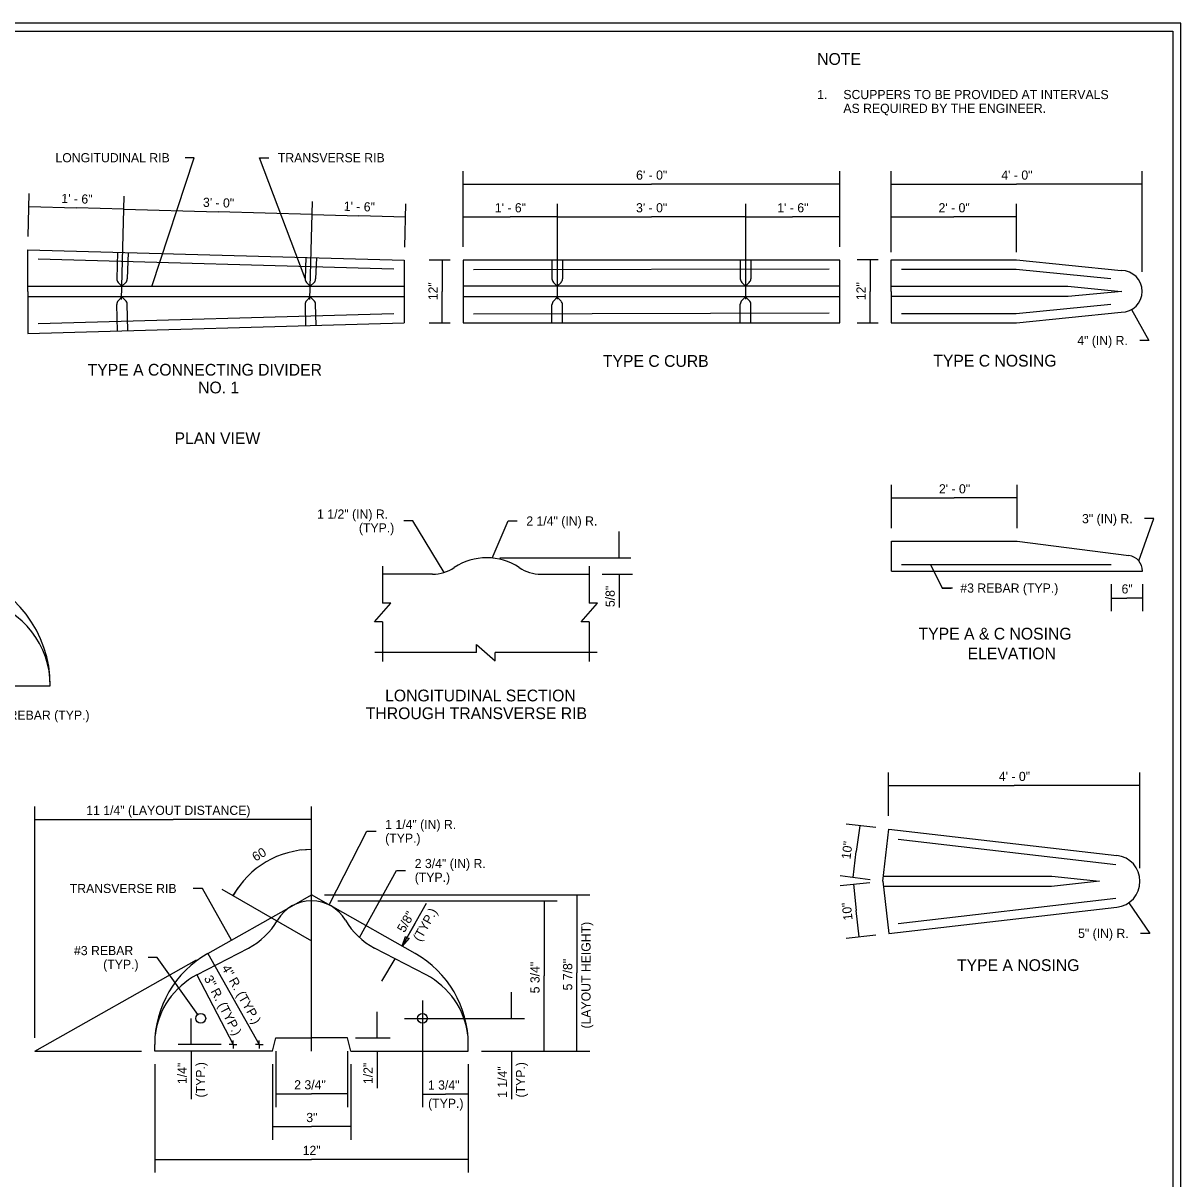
# Model space of a CAD drawing. Extents: x 99988 to 100172, y 99995 to 100047.
# Drawn here: x 100006.96 to 100015.81, y 100001.6 to 100010.44 of the extents above; entities that cross this region are included whole.
import ezdxf

# ---------------------------------------------------------------- set-up
doc = ezdxf.new("R2010")
doc.units = 0
for name, color, linetype in [('Level 1', 7, 'Continuous'), ('Level 15', 7, 'Continuous'), ('Level 2', 7, 'Continuous'), ('Level 20', 7, 'Continuous'), ('Level 27', 7, 'Continuous'), ('Level 3', 7, 'Continuous'), ('SH_GI_PlotLimits', 7, 'Continuous'), ('SH_GI_SheetBorder', 7, 'Continuous'), ('SH_RS_ConstructionNoteFlag', 7, 'Continuous'), ('SH_RS_DimensionLines', 7, 'Continuous')]:
    doc.layers.add(name, color=color, linetype=linetype)

msp = doc.modelspace()

# ---------------------------------------------------------------- linework, layer by layer
at = {"layer": 'Level 1'}
for centre in [(100008.318, 100002.8241), (100010.0134, 100002.8241)]:
    msp.add_circle(centre, 0.0375, dxfattribs=at)
at = {"layer": 'Level 15'}
for p, q in [((100010.324, 100008.7252), (100010.324, 100009.3052)), ((100013.204, 100008.7252), (100013.204, 100009.3052)), ((100013.5969, 100008.6857), (100013.5969, 100009.3052)), ((100015.5169, 100008.536), (100015.5169, 100009.3052)), ((100010.324, 100009.2052), (100011.764, 100009.2052)), ((100013.204, 100009.2052), (100011.764, 100009.2052)), ((100013.5969, 100009.2052), (100014.5569, 100009.2052)), ((100015.5169, 100009.2052), (100014.5569, 100009.2052)), ((100006.9972, 100008.8043), (100007.0063, 100009.1342)), ((100007.7116, 100008.3239), (100007.7335, 100009.114)), ((100007.0036, 100009.0342), (100007.3672, 100009.0241)), ((100007.7308, 100009.014), (100007.3672, 100009.0241)), ((100007.7308, 100009.014), (100008.4502, 100008.994)), ((100009.1697, 100008.9741), (100008.4502, 100008.994)), ((100009.1516, 100008.3239), (100009.1724, 100009.074)), ((100009.8772, 100008.7243), (100009.8863, 100009.0542)), ((100011.0441, 100009.0552), (100011.0441, 100008.3255)), ((100012.4836, 100009.0552), (100012.4836, 100008.3255)), ((100014.5569, 100008.6857), (100014.5569, 100009.0552)), ((100009.1697, 100008.9741), (100009.5266, 100008.9641)), ((100009.8836, 100008.9542), (100009.5266, 100008.9641)), ((100010.324, 100008.9552), (100010.684, 100008.9552)), ((100011.0441, 100008.9552), (100010.684, 100008.9552)), ((100011.0441, 100008.9552), (100011.7638, 100008.9552)), ((100012.4836, 100008.9552), (100011.7638, 100008.9552)), ((100012.4836, 100008.9752), (100012.4837, 100008.9752)), ((100012.4836, 100008.9552), (100012.8438, 100008.9552)), ((100013.204, 100008.9552), (100012.8438, 100008.9552)), ((100013.5969, 100008.9552), (100014.0769, 100008.9552)), ((100014.5569, 100008.9552), (100014.0769, 100008.9552)), ((100010.224, 100008.6252), (100010.064, 100008.6252)), ((100010.164, 100008.6252), (100010.164, 100008.3852)), ((100013.4969, 100008.6257), (100013.3369, 100008.6257)), ((100013.4369, 100008.6257), (100013.4369, 100008.3857)), ((100010.164, 100008.1452), (100010.164, 100008.3852)), ((100013.4369, 100008.1457), (100013.4369, 100008.3857)), ((100010.064, 100008.1452), (100010.224, 100008.1452)), ((100013.3369, 100008.1457), (100013.4969, 100008.1457)), ((100013.6, 100006.5752), (100013.6, 100006.9052)), ((100014.56, 100006.5752), (100014.56, 100006.9052)), ((100013.6, 100006.8052), (100014.08, 100006.8052)), ((100014.56, 100006.8052), (100014.08, 100006.8052)), ((100010.605, 100006.3477), (100011.6059, 100006.3477)), ((100009.7085, 100006.2827), (100009.7085, 100006)), ((100011.2885, 100006.2827), (100011.2885, 100006)), ((100011.3885, 100006.2227), (100011.6185, 100006.2227)), ((100014.0663, 100006.116), (100013.9863, 100006.116)), ((100015.52, 100006.1452), (100015.52, 100005.9397)), ((100009.6462, 100005.8565), (100009.7708, 100006)), ((100009.7708, 100006), (100009.7085, 100006)), ((100011.2262, 100005.8565), (100011.3508, 100006)), ((100011.3508, 100006), (100011.2885, 100006)), ((100009.7085, 100005.8565), (100009.6462, 100005.8565)), ((100009.7085, 100005.8565), (100009.7085, 100005.5549)), ((100011.2885, 100005.8565), (100011.2262, 100005.8565)), ((100011.2885, 100005.8565), (100011.2885, 100005.5549)), ((100010.4267, 100005.6227), (100010.4267, 100005.685)), ((100010.4267, 100005.685), (100010.5703, 100005.5604)), ((100010.4267, 100005.6227), (100009.6485, 100005.6227)), ((100011.3485, 100005.6227), (100010.5703, 100005.6227)), ((100010.5703, 100005.5604), (100010.5703, 100005.6227)), ((100013.5765, 100004.3737), (100013.5765, 100004.7054)), ((100015.5001, 100003.9726), (100015.5001, 100004.7054)), ((100013.5765, 100004.6054), (100014.5383, 100004.6054)), ((100015.5001, 100004.6054), (100014.5383, 100004.6054)), ((100007.0499, 100002.6742), (100007.0499, 100004.4459)), ((100009.1647, 100002.5742), (100009.1647, 100004.4459)), ((100007.0499, 100004.3459), (100008.1073, 100004.3459)), ((100009.1647, 100004.3459), (100008.1073, 100004.3459)), ((100013.357, 100004.2973), (100013.3292, 100004.1005)), ((100009.1647, 100004.1158), (100009.0899, 100004.1117)), ((100013.3069, 100003.903), (100013.3292, 100004.1005)), ((100008.4793, 100003.8133), (100009.1647, 100003.4176)), ((100008.5659, 100003.7633), (100008.6056, 100003.8265)), ((100013.3082, 100003.8501), (100013.3304, 100003.6487)), ((100009.2647, 100003.7687), (100011.2936, 100003.7687)), ((100009.3661, 100003.7242), (100011.0436, 100003.7242)), ((100010.9436, 100003.7242), (100010.9436, 100003.1492)), ((100011.1936, 100003.7687), (100011.1936, 100003.1715)), ((100013.3531, 100003.4475), (100013.3304, 100003.6487)), ((100009.8593, 100003.3757), (100009.938, 100003.5152)), ((100008.3725, 100003.3209), (100008.7658, 100002.6242)), ((100008.2877, 100003.1565), (100008.5647, 100002.6242)), ((100011.1936, 100002.5742), (100011.1936, 100003.1715)), ((100010.9436, 100002.5742), (100010.9436, 100003.1492)), ((100010.6936, 100002.8241), (100010.6936, 100003.0241)), ((100008.2455, 100002.6242), (100008.2455, 100002.8242)), ((100009.6674, 100002.6742), (100009.6674, 100002.8742)), ((100008.4747, 100002.6242), (100008.1455, 100002.6242)), ((100009.5025, 100002.6742), (100009.7674, 100002.6742)), ((100008.8912, 100002.5742), (100008.8912, 100002.146)), ((100010.4636, 100002.5742), (100011.2936, 100002.5742)), ((100007.9658, 100002.4742), (100007.9658, 100001.6442)), ((100008.8662, 100002.4742), (100008.8662, 100001.8959)), ((100009.4657, 100002.4742), (100009.4657, 100001.8959)), ((100010.3636, 100002.4742), (100010.3636, 100001.6442)), ((100008.8912, 100002.246), (100009.166, 100002.246)), ((100009.4407, 100002.246), (100009.166, 100002.246)), ((100010.0134, 100002.2442), (100010.1885, 100002.2442)), ((100010.3636, 100002.2442), (100010.1885, 100002.2442)), ((100008.8662, 100001.9959), (100009.166, 100001.9959)), ((100009.4657, 100001.9959), (100009.166, 100001.9959)), ((100007.9658, 100001.7442), (100009.1647, 100001.7442)), ((100010.3636, 100001.7442), (100009.1647, 100001.7442))]:
    msp.add_line(p, q, dxfattribs=at)
for points in [[(100007.9439, 100008.4239), (100008.2686, 100009.4081), (100008.1986, 100009.4081)], [(100009.1159, 100008.4829), (100008.7676, 100009.4081), (100008.8376, 100009.4081)], [(100015.4353, 100008.2463), (100015.5685, 100008.0093), (100015.4985, 100008.0093)], [(100010.1787, 100006.236), (100009.9406, 100006.6292), (100009.8706, 100006.6292)], [(100010.5458, 100006.3459), (100010.6675, 100006.6292), (100010.7375, 100006.6292)], [(100015.4902, 100006.3244), (100015.6049, 100006.6471), (100015.5349, 100006.6471)], [(100013.8993, 100006.2952), (100013.9863, 100006.116), (100014.0563, 100006.116)], [(100015.28, 100006.1452), (100015.28, 100005.9397)], [(100009.3009, 100003.6915), (100009.5881, 100004.2551), (100009.6581, 100004.2551)], [(100009.5306, 100003.4431), (100009.8142, 100003.9561), (100009.8842, 100003.9561)], [(100008.5519, 100003.4221), (100008.3305, 100003.818), (100008.2605, 100003.818)], [(100015.4137, 100003.708), (100015.5747, 100003.4746), (100015.5047, 100003.4746)], [(100008.2962, 100002.8547), (100007.9852, 100003.29), (100007.9152, 100003.29)]]:
    msp.add_lwpolyline(points, dxfattribs=at)
msp.add_lwpolyline([(100009.8593, 100003.3757), (100009.8845, 100003.4517), (100009.8961, 100003.441), (100009.9113, 100003.4366)], close=True, dxfattribs=at)
msp.add_arc((100009.1647, 100003.431), 0.6849, 90, 150.96723, dxfattribs=at)
at = {"layer": 'Level 2'}
for p, q in [((100006.9944, 100008.3844), (100006.9944, 100008.7044)), ((100006.9944, 100008.7044), (100009.8744, 100008.6244)), ((100007.6813, 100008.6865), (100007.6756, 100008.4827)), ((100007.7619, 100008.682), (100007.7563, 100008.4805)), ((100009.1211, 100008.6453), (100009.1159, 100008.4829)), ((100009.2018, 100008.6418), (100009.1966, 100008.4803)), ((100009.7944, 100008.556), (100007.0744, 100008.6309)), ((100009.8744, 100008.6244), (100009.8744, 100008.1444)), ((100013.124, 100008.5557), (100010.404, 100008.5495)), ((100011.0036, 100008.6252), (100011.0036, 100008.4825)), ((100011.0844, 100008.6252), (100011.0844, 100008.4825)), ((100012.4436, 100008.6252), (100012.4436, 100008.4825)), ((100012.5244, 100008.6252), (100012.5244, 100008.4825)), ((100007.7144, 100008.4247), (100007.6865, 100008.4541)), ((100007.7144, 100008.4247), (100007.7438, 100008.4525)), ((100009.1544, 100008.4247), (100009.1267, 100008.4543)), ((100009.1544, 100008.4247), (100009.184, 100008.4524)), ((100011.044, 100008.4255), (100011.0153, 100008.4542)), ((100011.044, 100008.4255), (100011.0727, 100008.4542)), ((100012.484, 100008.4255), (100012.4553, 100008.4542)), ((100012.484, 100008.4255), (100012.5127, 100008.4542)), ((100013.5969, 100008.3857), (100013.5969, 100008.1457)), ((100007.6809, 100008.0821), (100007.675, 100008.2856)), ((100007.7138, 100008.3437), (100007.6859, 100008.3142)), ((100007.7138, 100008.3437), (100007.7432, 100008.3158)), ((100007.7615, 100008.0867), (100007.7558, 100008.2879)), ((100009.1151, 100008.2856), (100009.1199, 100008.1199)), ((100009.1538, 100008.3437), (100009.126, 100008.3142)), ((100009.1538, 100008.3437), (100009.1833, 100008.3158)), ((100009.2005, 100008.1267), (100009.1958, 100008.2879)), ((100011.044, 100008.3405), (100011.0153, 100008.3119)), ((100011.044, 100008.3405), (100011.0727, 100008.3119)), ((100012.4436, 100008.1452), (100012.4436, 100008.2879)), ((100012.484, 100008.3448), (100012.4553, 100008.3162)), ((100012.484, 100008.3448), (100012.5127, 100008.3162)), ((100012.5244, 100008.1453), (100012.5244, 100008.2879)), ((100009.7944, 100008.2132), (100007.0744, 100008.1382)), ((100013.124, 100008.218), (100010.404, 100008.2118)), ((100011.0036, 100008.1452), (100011.0036, 100008.2836)), ((100011.0844, 100008.1452), (100011.0844, 100008.2836)), ((100014.56, 100006.4752), (100015.4155, 100006.3642)), ((100013.6769, 100006.2952), (100015.28, 100006.2952)), ((100010.0904, 100006.2227), (100009.7085, 100006.2227)), ((100013.6, 100006.2452), (100015.52, 100006.2452)), ((100005.255, 100005.3684), (100007.1675, 100005.3684)), ((100013.5349, 100003.8726), (100013.5801, 100004.2726)), ((100013.5801, 100004.2726), (100015.3231, 100004.0713)), ((100013.6518, 100004.194), (100015.3151, 100004.0019)), ((100013.5349, 100003.8726), (100013.5801, 100003.4726)), ((100008.3725, 100003.3209), (100009.033, 100003.6938)), ((100009.033, 100003.6938), (100009.1647, 100003.7681)), ((100009.3114, 100003.6859), (100009.1647, 100003.7681)), ((100013.6518, 100003.5512), (100015.3151, 100003.7434)), ((100009.9569, 100003.3209), (100009.3275, 100003.6762)), ((100013.5801, 100003.4726), (100015.3231, 100003.6739)), ((100008.2877, 100003.1565), (100008.6824, 100003.3618)), ((100010.0417, 100003.1565), (100009.647, 100003.3618)), ((100007.0499, 100002.5742), (100008.2854, 100003.2717)), ((100008.3725, 100003.3209), (100008.3725, 100003.3209)), ((100010.0134, 100002.9616), (100010.0134, 100002.1442)), ((100010.258, 100002.9657), (100010.258, 100002.9657)), ((100009.8759, 100002.8241), (100010.7936, 100002.8241)), ((100007.9658, 100002.5742), (100007.9658, 100002.6242)), ((100008.5647, 100002.6242), (100008.5347, 100002.6242)), ((100008.5647, 100002.6242), (100008.5647, 100002.6542)), ((100008.5647, 100002.6242), (100008.5647, 100002.5942)), ((100008.5647, 100002.6242), (100008.5947, 100002.6242)), ((100008.7658, 100002.6242), (100008.7358, 100002.6242)), ((100008.7658, 100002.6242), (100008.7658, 100002.6542)), ((100008.7658, 100002.6242), (100008.7658, 100002.5942)), ((100008.7658, 100002.6242), (100008.7958, 100002.6242)), ((100008.8662, 100002.5742), (100008.8912, 100002.6742)), ((100009.4407, 100002.6742), (100009.1657, 100002.6742)), ((100009.4657, 100002.5742), (100009.4407, 100002.6742)), ((100010.3636, 100002.5742), (100010.3636, 100002.6242)), ((100007.0499, 100002.5742), (100007.8658, 100002.5742)), ((100008.8662, 100002.5742), (100007.9658, 100002.5742)), ((100009.4407, 100002.5742), (100009.4407, 100002.1522)), ((100009.4657, 100002.5742), (100010.3636, 100002.5742)), ((100009.4407, 100002.1824), (100009.4407, 100002.146))]:
    msp.add_line(p, q, dxfattribs=at)
for points in [[(100010.324, 100008.1452), (100013.204, 100008.1452), (100013.204, 100008.6252), (100010.324, 100008.6252), (100010.324, 100008.1452)], [(100013.5969, 100008.6257), (100014.5569, 100008.6257), (100015.3569, 100008.5457)], [(100013.5969, 100008.3857), (100013.5969, 100008.6257)], [(100013.5969, 100008.6257), (100014.5569, 100008.6257), (100015.3569, 100008.5457)], [(100013.6769, 100008.5559), (100014.5534, 100008.5559), (100015.2769, 100008.4835)], [(100006.9944, 100008.3844), (100006.9944, 100008.0644), (100009.8744, 100008.1444)], [(100013.6769, 100008.2156), (100014.5534, 100008.2156), (100015.2769, 100008.288)], [(100013.5969, 100008.1457), (100014.5569, 100008.1457), (100015.3569, 100008.2257)], [(100013.6, 100006.2452), (100013.6, 100006.4752), (100014.56, 100006.4752)], [(100010.9195, 100006.2227), (100011.2885, 100006.2227)], [(100008.8912, 100002.6742), (100009.1662, 100002.6742)], [(100009.4407, 100002.6742), (100009.1657, 100002.6742)]]:
    msp.add_lwpolyline(points, dxfattribs=at)
for centre, radius, start, end in [((100007.7156, 100008.4816), 0.04, 178.40886, 223.40886), ((100007.7164, 100008.4816), 0.04, 313.40886, 358.40886), ((100009.1559, 100008.4816), 0.04, 178.15574, 223.15574), ((100009.1566, 100008.4816), 0.04, 313.15574, 358.15574), ((100011.0436, 100008.4825), 0.04, 180, 225), ((100011.0444, 100008.4825), 0.04, 315, 0), ((100012.4836, 100008.4825), 0.04, 180, 225), ((100012.4844, 100008.4825), 0.04, 315, 0), ((100015.3569, 100008.3857), 0.16, 270, 90), ((100007.715, 100008.2867), 0.04, 136.64208, 181.64208), ((100007.7158, 100008.2867), 0.04, 1.64208, 46.64208), ((100009.1551, 100008.2867), 0.04, 136.678, 181.678), ((100009.1558, 100008.2867), 0.04, 1.678, 46.678), ((100011.0436, 100008.2836), 0.04, 135, 180), ((100011.0444, 100008.2836), 0.04, 0, 45), ((100012.4836, 100008.2879), 0.04, 135, 180), ((100012.4844, 100008.2879), 0.04, 0, 45), ((100010.505, 100005.8977), 0.45, 56.44269, 123.55731), ((100015.4, 100006.2452), 0.12, 0, 82.60746), ((100010.0904, 100006.5227), 0.3, 270, 303.55731), ((100010.9195, 100006.5227), 0.3, 236.44269, 270), ((100006.2675, 100005.3684), 0.9, 0, 74.83771), ((100006.4925, 100005.3684), 0.675, 0, 75.66199), ((100015.3001, 100003.8726), 0.2, 276.58881, 83.41119), ((100009.1647, 100003.4242), 0.3, 90, 149.97217), ((100009.1647, 100003.4242), 0.3, 30.02783, 90), ((100008.4285, 100003.8497), 0.55, 297.49016, 329.97217), ((100009.9009, 100003.8497), 0.55, 210.02783, 242.50984), ((100008.7658, 100002.6242), 0.8, 119.44692, 180), ((100009.5636, 100002.6242), 0.8, 0, 60.55308), ((100008.5647, 100002.6242), 0.6, 117.49125, 173.12025), ((100009.7647, 100002.6242), 0.6, 6.87975, 62.50875)]:
    msp.add_arc(centre, radius, start, end, dxfattribs=at)
at = {"layer": 'Level 27'}
for p, q in [((100009.8744, 100008.4239), (100006.9944, 100008.4239)), ((100013.1969, 100008.4255), (100010.324, 100008.4255)), ((100013.5969, 100008.4261), (100014.9473, 100008.4261)), ((100014.9473, 100008.4261), (100015.3569, 100008.3857)), ((100015.3609, 100008.3857), (100014.9513, 100008.3454)), ((100009.8744, 100008.344), (100006.9944, 100008.344)), ((100013.1965, 100008.3448), (100010.324, 100008.3448)), ((100014.9513, 100008.3454), (100013.5969, 100008.3454)), ((100013.5395, 100003.913), (100014.825, 100003.913)), ((100015.1917, 100003.8726), (100014.8233, 100003.8323)), ((100014.825, 100003.913), (100015.1917, 100003.8728)), ((100014.8233, 100003.8323), (100013.5395, 100003.8323))]:
    msp.add_line(p, q, dxfattribs=at)
at = {"layer": 'Level 3'}
for p, q in [((100013.4808, 100004.2837), (100013.2522, 100004.3092)), ((100013.4357, 100003.8852), (100013.2075, 100003.9142)), ((100013.4355, 100003.8623), (100013.2083, 100003.8388)), ((100013.4808, 100003.4616), (100013.2538, 100003.4362))]:
    msp.add_line(p, q, dxfattribs=at)
at = {"layer": 'SH_GI_PlotLimits'}
msp.add_lwpolyline([(99999.3125, 99999.9375), (100015.8125, 99999.9375), (100015.8125, 100010.4375), (99999.3125, 100010.4375)], close=True, dxfattribs=at)
at = {"layer": 'SH_GI_SheetBorder'}
for p, q in [((100000, 100010.375), (100015.75, 100010.375)), ((100015.75, 100010.375), (100015.75, 100000))]:
    msp.add_line(p, q, dxfattribs=at)
at = {"layer": 'SH_RS_DimensionLines'}
for p, q in [((100011.5185, 100006.3477), (100011.5185, 100006.5477)), ((100011.5185, 100006.2227), (100011.5185, 100005.9666)), ((100015.28, 100006.0397), (100015.4, 100006.0397)), ((100015.52, 100006.0397), (100015.4, 100006.0397)), ((100009.8593, 100003.3757), (100010.0451, 100003.7049)), ((100009.8593, 100003.3757), (100009.9576, 100003.5498)), ((100009.803, 100003.2806), (100009.7012, 100003.1085)), ((100008.2455, 100002.5742), (100008.2455, 100002.2058)), ((100009.6674, 100002.5742), (100009.6674, 100002.2915)), ((100010.6936, 100002.5742), (100010.6936, 100002.2058))]:
    msp.add_line(p, q, dxfattribs=at)

# ---------------------------------------------------------------- texts
at = {"layer": 'Level 20'}
for s, height, p in [('NOTE', 0.09, (100013.0318, 100010.1184)), ('1.', 0.07, (100013.0318, 100009.8564)), ('SCUPPERS TO BE PROVIDED AT INTERVALS', 0.07, (100013.2318, 100009.8564)), ('AS REQUIRED BY THE ENGINEER.', 0.07, (100013.2318, 100009.7508)), ('LONGITUDINAL RIB', 0.07, (100007.2068, 100009.3731)), ('6\' - 0"', 0.07, (100011.6468, 100009.2402)), ('4\' - 0"', 0.07, (100014.4397, 100009.2402)), ('1\' - 6"', 0.07, (100010.5668, 100008.9902)), ('3\' - 0"', 0.07, (100011.6466, 100008.9902)), ('2\' - 0"', 0.07, (100013.9597, 100008.9902)), ('4" (IN) R.', 0.07, (100015.0204, 100007.9743)), ('TYPE C CURB', 0.09, (100011.3927, 100007.8082)), ('TYPE C NOSING', 0.09, (100013.9193, 100007.8103)), ('TYPE A CONNECTING DIVIDER', 0.09, (100007.4528, 100007.741)), ('NO. 1', 0.09, (100008.2975, 100007.6053)), ('PLAN VIEW', 0.09, (100008.1176, 100007.2171)), ('1 1/2" (IN) R.', 0.07, (100009.2075, 100006.647)), ('(TYP.)', 0.07, (100009.5273, 100006.5414)), ('3" (IN) R.', 0.07, (100015.0569, 100006.6121)), ('6"', 0.07, (100015.3591, 100006.0747)), ('TYPE A & C NOSING', 0.09, (100013.8067, 100005.7222)), ('ELEVATION', 0.09, (100014.1818, 100005.5707)), ('LONGITUDINAL SECTION', 0.09, (100009.7275, 100005.2491)), ('THROUGH TRANSVERSE RIB', 0.09, (100009.5797, 100005.1134)), ('4\' - 0"', 0.07, (100014.4211, 100004.6404)), ('11 1/4" (LAYOUT DISTANCE)', 0.07, (100007.4422, 100004.3809)), ('TRANSVERSE RIB', 0.07, (100007.3162, 100003.783)), ('5" (IN) R.', 0.07, (100015.0267, 100003.4396)), ('#3 REBAR', 0.07, (100007.3488, 100003.3078)), ('(TYP.)', 0.07, (100007.5719, 100003.2022)), ('TYPE A NOSING', 0.09, (100014.1006, 100003.1863)), ('(TYP.)', 0.07, (100010.0565, 100002.1392)), ('3"', 0.07, (100009.125, 100002.0309)), ('12"', 0.07, (100009.0973, 100001.7792))]:
    msp.add_text(s, height=height, dxfattribs=at).set_placement(p)
for s, rotation, p in [('TRANSVERSE RIB', 360, (100008.9076, 100009.3731)), ('1\' - 6"', 358.40886, (100007.251, 100009.0624)), ('3\' - 0"', 358.40886, (100008.334, 100009.0323)), ('1\' - 6"', 358.40886, (100009.4104, 100009.0024)), ('1\' - 6"', 360, (100012.7266, 100008.9902)), ('12"', 90, (100010.129, 100008.3178)), ('12"', 90, (100013.4019, 100008.3183)), ('2\' - 0"', 360, (100013.9628, 100006.8402)), ('2 1/4" (IN) R.', 360, (100010.8075, 100006.5942)), ('#3 REBAR (TYP.)', 360, (100014.1263, 100006.081)), ('#3 REBAR (TYP.)', 360, (100006.7184, 100005.1089)), ('1 1/4" (IN) R.', 360, (100009.7281, 100004.2729)), ('(TYP.)', 360, (100009.7281, 100004.1674)), ('60', 30.62288, (100008.7371, 100004.0224)), ('10"', 82.83008, (100013.2861, 100004.038)), ('2 3/4" (IN) R.', 360, (100009.9542, 100003.9739)), ('(TYP.)', 360, (100009.9542, 100003.8683)), ('10"', 96.37186, (100013.3031, 100003.5779)), ('(LAYOUT HEIGHT)', 90, (100011.2986, 100002.7463)), ('5 3/4"', 90, (100010.9086, 100003.0157)), ('5 7/8"', 90, (100011.1586, 100003.038)), ('3" R. (TYP.)', 297.49125, (100008.3405, 100003.1309)), ('4" R. (TYP.)', 299.44692, (100008.4753, 100003.21)), ('2 3/4"', 360, (100009.0325, 100002.281)), ('1 3/4"', 360, (100010.055, 100002.2792))]:
    msp.add_text(s, height=0.07, rotation=rotation, dxfattribs=at).set_placement(p)
at = {"layer": 'SH_RS_ConstructionNoteFlag'}
for s, rotation, p in [('5/8"', 90, (100011.4835, 100005.9704)), ('5/8"', 60.55289, (100009.8755, 100003.4756)), ('(TYP.)', 60.55289, (100009.9974, 100003.4067)), ('1/4"', 90, (100008.2105, 100002.3218)), ('(TYP.)', 90, (100008.3505, 100002.219)), ('1/2"', 90, (100009.6324, 100002.3218)), ('1 1/4"', 90, (100010.6586, 100002.2161)), ('(TYP.)', 90, (100010.7986, 100002.219))]:
    msp.add_text(s, height=0.07, rotation=rotation, dxfattribs=at).set_placement(p)

doc.saveas('drawing.dxf')
